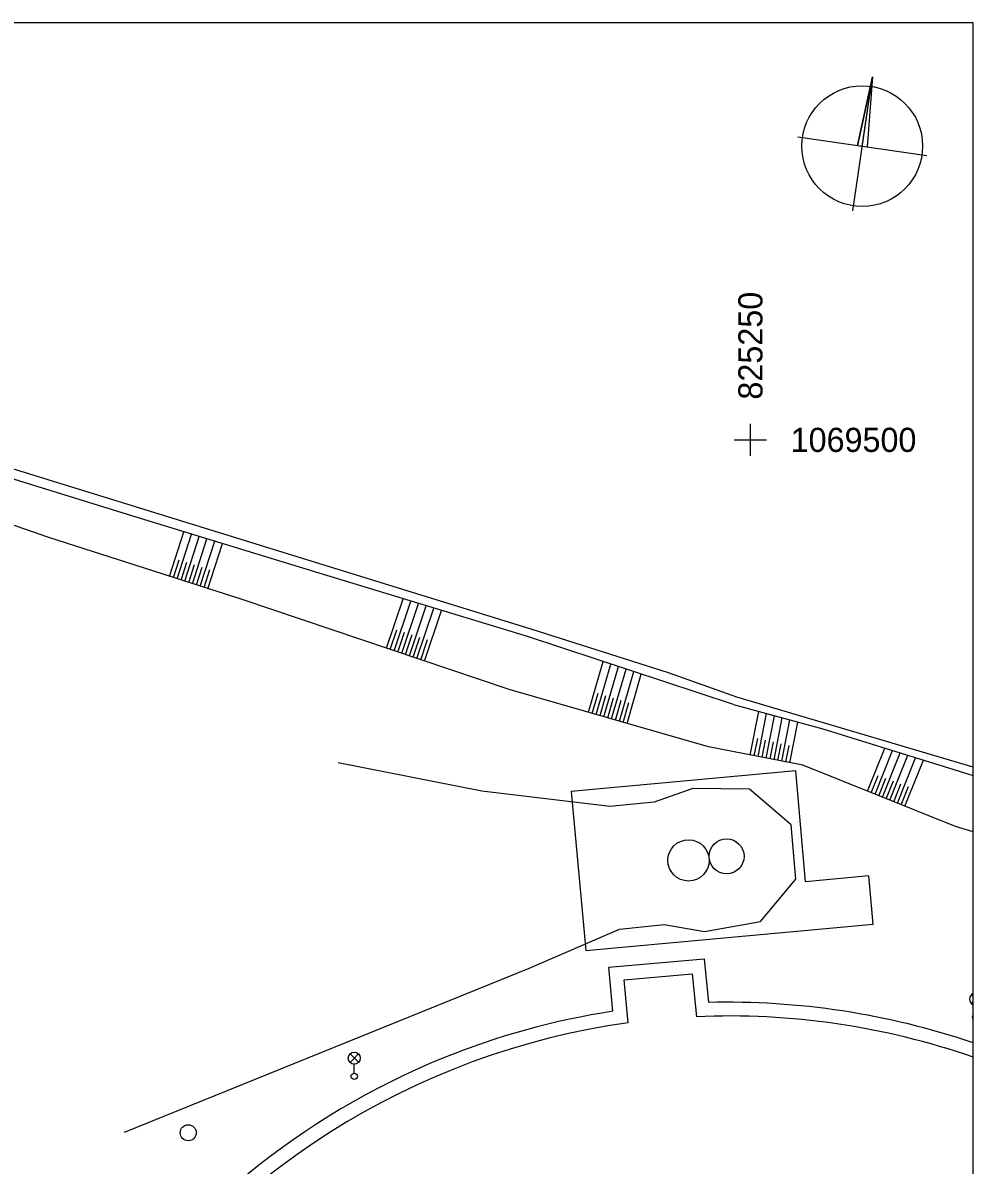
# Model space of a CAD drawing. Extents: x -825369 to -825236, y -1069674 to -1069474.
# Drawn here: x -825295.2 to -825236.2, y -1069545 to -1069474.1 of the extents above; entities that cross this region are included whole.
import ezdxf

# ---------------------------------------------------------------- set-up
doc = ezdxf.new("R2010")
doc.units = 0
for name, color, linetype in [('Vrstva 12', 7, 'Continuous'), ('Vrstva 15', 7, 'Continuous'), ('Vrstva 20', 7, 'Continuous'), ('Vrstva 30', 7, 'Continuous'), ('Vrstva 39', 7, 'Continuous'), ('Vrstva 40', 7, 'Continuous'), ('Vrstva 41', 7, 'Continuous'), ('Vrstva 42', 7, 'Continuous'), ('Vrstva 63', 7, 'Continuous'), ('Vrstva 8', 7, 'Continuous')]:
    doc.layers.add(name, color=color, linetype=linetype)

msp = doc.modelspace()

# ---------------------------------------------------------------- linework, layer by layer
at = {"layer": 'Vrstva 12'}
for p, q in [((-825236.167, -1069534.561), (-825236.278, -1069534.45)), ((-825236.167, -1069535.065), (-825236.167, -1069534.373)), ((-825236.286, -1069534.982), (-825236.167, -1069534.863)), ((-825236.167, -1069535.982), (-825236.167, -1069535.706)), ((-825274.862, -1069538.651), (-825274.334, -1069538.123)), ((-825274.326, -1069538.648), (-825274.854, -1069538.119)), ((-825274.598, -1069539.313), (-825274.598, -1069538.763))]:
    msp.add_line(p, q, dxfattribs=at)
for centre, radius in [((-825274.598, -1069538.388), 0.375), ((-825274.598, -1069539.513), 0.2)]:
    msp.add_circle(centre, radius, dxfattribs=at)
for centre, radius, start, end in [((-825236.022, -1069534.719), 0.375, 112.72874, 247.27126), ((-825236.022, -1069535.844), 0.2, 136.42239, 223.57761)]:
    msp.add_arc(centre, radius, start, end, dxfattribs=at)
at = {"layer": 'Vrstva 15'}
msp.add_lwpolyline([(-825257.6, -1069536.19), (-825257.83, -1069533.52), (-825253.62, -1069533.14), (-825253.35, -1069535.81)], dxfattribs=at)
for centre, radius, start, end in [((-825251.142, -1069582.373), 46.632, 97.96011, 146.77246), ((-825251.346, -1069582.202), 46.435, 70.92039, 92.47402)]:
    msp.add_arc(centre, radius, start, end, dxfattribs=at)
at = {"layer": 'Vrstva 20'}
for centre, radius in [((-825253.842, -1069526.107), 1.281), ((-825251.481, -1069525.858), 1.085)]:
    msp.add_circle(centre, radius, dxfattribs=at)
at = {"layer": 'Vrstva 30'}
msp.add_lwpolyline([(-825261.124, -1069521.831), (-825260.219, -1069531.694), (-825242.384, -1069530.073), (-825242.647, -1069527.063), (-825246.583, -1069527.436), (-825247.181, -1069520.55)], close=True, dxfattribs=at)
msp.add_lwpolyline([(-825258.542, -1069535.476), (-825258.786, -1069532.742), (-825252.862, -1069532.209), (-825252.611, -1069534.928)], dxfattribs=at)
for centre, radius, start, end in [((-825251.42, -1069581.947), 47.013, 98.71297, 112.08193), ((-825251.433, -1069582.443), 47.53, 71.26489, 91.41997), ((-825251.168, -1069582.34), 47.473, 112.18499, 146.31395)]:
    msp.add_arc(centre, radius, start, end, dxfattribs=at)
at = {"layer": 'Vrstva 39'}
for p, q in [((-825263.556, -1069511.779), (-825302.149, -1069499.836)), ((-825255.09, -1069514.467), (-825263.556, -1069511.779)), ((-825250.836, -1069515.964), (-825255.09, -1069514.467)), ((-825236.167, -1069520.325), (-825250.836, -1069515.964))]:
    msp.add_line(p, q, dxfattribs=at)
msp.add_lwpolyline([(-825288.865, -1069542.983), (-825263.775, -1069532.818), (-825258.136, -1069530.369), (-825255.36, -1069530.096), (-825252.86, -1069530.514), (-825249.376, -1069529.901), (-825247.174, -1069527.263), (-825247.462, -1069523.904), (-825250.047, -1069521.686), (-825253.568, -1069521.651), (-825255.985, -1069522.5), (-825258.739, -1069522.759), (-825266.685, -1069521.801), (-825275.59, -1069520.057)], dxfattribs=at)
at = {"layer": 'Vrstva 40'}
msp.add_lwpolyline([(-825236.167, -1069524.332), (-825237.262, -1069523.999), (-825246.754, -1069520.202), (-825252.607, -1069519.062), (-825264.972, -1069515.496), (-825281.569, -1069509.919), (-825293.563, -1069506.065), (-825302.711, -1069502.888)], dxfattribs=at)
at = {"layer": 'Vrstva 41'}
for points in [[(-825251.05, -1069516.429), (-825263.841, -1069512.216), (-825276.773, -1069508.276), (-825287.871, -1069504.889), (-825302.141, -1069500.473)], [(-825251.05, -1069516.429), (-825245.494, -1069517.947), (-825236.167, -1069520.84)]]:
    msp.add_lwpolyline(points, dxfattribs=at)
at = {"layer": 'Vrstva 42'}
for p, q in [((-825286.068, -1069508.473), (-825285.181, -1069505.71)), ((-825285.592, -1069508.626), (-825284.702, -1069505.856)), ((-825285.116, -1069508.779), (-825284.224, -1069506.002)), ((-825284.64, -1069508.932), (-825283.746, -1069506.148)), ((-825284.164, -1069509.085), (-825283.267, -1069506.294)), ((-825283.688, -1069509.238), (-825282.789, -1069506.44)), ((-825285.83, -1069508.55), (-825285.475, -1069507.444)), ((-825285.354, -1069508.703), (-825284.998, -1069507.595)), ((-825284.878, -1069508.856), (-825284.521, -1069507.745)), ((-825284.402, -1069509.009), (-825284.044, -1069507.895)), ((-825283.926, -1069509.162), (-825283.568, -1069508.045)), ((-825272.601, -1069512.932), (-825271.569, -1069509.861)), ((-825272.127, -1069513.092), (-825271.091, -1069510.007)), ((-825271.653, -1069513.251), (-825270.612, -1069510.153)), ((-825271.179, -1069513.41), (-825270.134, -1069510.299)), ((-825270.705, -1069513.57), (-825269.655, -1069510.445)), ((-825270.231, -1069513.729), (-825269.177, -1069510.59)), ((-825272.364, -1069513.012), (-825271.951, -1069511.784)), ((-825271.89, -1069513.171), (-825271.475, -1069511.938)), ((-825271.416, -1069513.331), (-825271, -1069512.091)), ((-825270.942, -1069513.49), (-825270.524, -1069512.245)), ((-825270.468, -1069513.649), (-825270.048, -1069512.399)), ((-825260.058, -1069516.913), (-825259.149, -1069513.761)), ((-825259.578, -1069517.052), (-825258.674, -1069513.918)), ((-825259.098, -1069517.19), (-825258.199, -1069514.074)), ((-825258.617, -1069517.329), (-825257.724, -1069514.231)), ((-825258.137, -1069517.467), (-825257.248, -1069514.387)), ((-825257.656, -1069517.606), (-825256.773, -1069514.544)), ((-825259.818, -1069516.982), (-825259.455, -1069515.722)), ((-825259.338, -1069517.121), (-825258.976, -1069515.867)), ((-825258.857, -1069517.259), (-825258.498, -1069516.013)), ((-825258.377, -1069517.398), (-825258.02, -1069516.159)), ((-825257.896, -1069517.537), (-825257.541, -1069516.305)), ((-825250.005, -1069519.569), (-825249.477, -1069516.859)), ((-825249.514, -1069519.664), (-825248.993, -1069516.991)), ((-825249.023, -1069519.76), (-825248.51, -1069517.123)), ((-825248.532, -1069519.856), (-825248.026, -1069517.255)), ((-825248.042, -1069519.951), (-825247.542, -1069517.387)), ((-825247.551, -1069520.047), (-825247.059, -1069517.519)), ((-825249.759, -1069519.617), (-825249.548, -1069518.533)), ((-825249.269, -1069519.712), (-825249.06, -1069518.643)), ((-825248.778, -1069519.808), (-825248.572, -1069518.753)), ((-825248.287, -1069519.903), (-825248.085, -1069518.863)), ((-825247.796, -1069519.999), (-825247.597, -1069518.973)), ((-825242.725, -1069521.814), (-825241.654, -1069519.138)), ((-825242.26, -1069522), (-825241.175, -1069519.287)), ((-825241.796, -1069522.185), (-825240.696, -1069519.435)), ((-825241.332, -1069522.371), (-825240.217, -1069519.584)), ((-825240.868, -1069522.557), (-825239.738, -1069519.733)), ((-825240.403, -1069522.742), (-825239.259, -1069519.881)), ((-825242.492, -1069521.907), (-825242.064, -1069520.836)), ((-825242.028, -1069522.092), (-825241.594, -1069521.007)), ((-825241.564, -1069522.278), (-825241.124, -1069521.178)), ((-825241.1, -1069522.464), (-825240.654, -1069521.349)), ((-825240.635, -1069522.65), (-825240.184, -1069521.52))]:
    msp.add_line(p, q, dxfattribs=at)
at = {"layer": 'Vrstva 63'}
for p, q in [((-825236.167, -1069474.111), (-825368.516, -1069474.111)), ((-825236.167, -1069673.689), (-825236.167, -1069474.111)), ((-825243.637, -1069485.772), (-825242.427, -1069477.46)), ((-825247.061, -1069481.181), (-825239.046, -1069482.347))]:
    msp.add_line(p, q, dxfattribs=at)
for points in [[(-825243.35, -1069481.721), (-825242.427, -1069477.46), (-825242.757, -1069481.807)], [(-825250, -1069501), (-825250, -1069500), (-825250, -1069499)], [(-825251, -1069500), (-825250, -1069500), (-825249, -1069500)]]:
    msp.add_lwpolyline(points, dxfattribs=at)
msp.add_lwpolyline([(-825243.35, -1069481.721), (-825243.054, -1069481.764), (-825242.427, -1069477.46)], close=True, dxfattribs=at)
msp.add_circle((-825243.054, -1069481.764), 3.75, dxfattribs=at)
at = {"layer": 'Vrstva 8'}
msp.add_circle((-825284.909, -1069543.017), 0.5, dxfattribs=at)

# ---------------------------------------------------------------- texts
at = {"layer": 'Vrstva 63'}
msp.add_text('825250', height=1.5, rotation=90, dxfattribs=at).set_placement((-825249.25, -1069497.5))
msp.add_text('1069500', height=1.5, dxfattribs=at).set_placement((-825247.5, -1069500.75))

doc.saveas('drawing.dxf')
